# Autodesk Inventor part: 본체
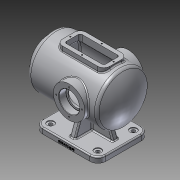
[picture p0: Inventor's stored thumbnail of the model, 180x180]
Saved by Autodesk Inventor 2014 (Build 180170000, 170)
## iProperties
Created: 2021-11
Part Number: 본체
Material: 알루미늄 6061
Document SubType Name: Modeling
Designer: kb542-04
Density: 2.71 g/cm^3
Appearance: 알루미늄 - 평지
Mass: 3553.65 g
Surface Area: 2404.16 cm^2
Volume: 1311.31 cm^3
Author: kb542-04
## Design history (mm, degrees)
sketch "스케치1"
  geometry: L1 (0, 0)-(210, 0); L2 (0, 32.5)-(25, 32.5); L3 (25, 32.5)-(25, 55); L4 (25, 55)-(181.239, 55); L5 (0, 32.5)-(0, 47.5); L6 (0, 47.5)-(10, 47.5); L7 (10, 47.5)-(10, 65); L8 (10, 65)-(181.239, 65); L9 (0, 101.95)-(170, 101.95); L10 (210, 0)-(210, 59.358); A1 r 100 centre (110, 0) between (210, 0) and (189.154, 61.111); A2 r 90 centre (110, 0) between (200, 0) and (181.239, 55); A3 r 10 centre (181.239, 55) between (189.154, 61.111) and (181.239, 65); 1 further point
  constraints: 20 end point, 7 point on circle, 5 parallel, 4 perpendicular, 3 centre point, 3 tangent, 2 point on line, 2 vertical alignment, 1 concentric, 1 horizontal
  dimensions: "d1" = 210 distance of L1.start L1.end; "d2" = 10 radial gap between concentric circles of A1 A2; "d3" = 25 distance of L2.start L2.end; "d4" = 65 diameter of L2 L1; "d5" = 95 diameter of L6 L1; "d6" = 130 diameter of L8 L1; "d7" = 10 distance between parallel lines of L7 L5; "d8" = 110 diameter of L4 L1; "d30" = 100 radius of A1; "d31" = 170 distance of L9.start L9.end; "d32" = 10 radius of A3
revolve "회전1" sketch "스케치1" stored, may be unused: angle "d10" = 90 deg
node "작업 평면1"
sketch "스케치2"
  geometry: L1 (50, -30)-(170, -30); L2 (170, -30)-(170, 30); L3 (170, 30)-(50, 30); L4 (50, 30)-(50, -30); L5 (60, -20)-(160, -20); L6 (160, -20)-(160, 20); L7 (160, 20)-(60, 20); L8 (60, 20)-(60, -20); 2 further points
  constraints: 16 end point, 4 parallel, 2 horizontal, 2 perpendicular, 1 horizontal alignment, 1 midpoint
  dimensions: "d12" = 120 distance of L2.end L3.end; "d13" = 10 distance between parallel lines of L7 L3; "d14" = 10 distance between parallel lines of L2 L6; "d15" = 10 distance between parallel lines of L4 L8; "d16" = 10 distance between parallel lines of L1 L5; "d17" = 50 distance from line of L4 point (0, 0); "d18" = 60 distance of L3.end L1.start
extrude "돌출1" join sketch "스케치2" stored distance "d19" = 10; taper "d20" = 0 deg
sketch "스케치3"
  geometry: L1 (170, 30)-(50, 30) reference; L2 (50, 30)-(50, -30) reference; L3 (50, -30)-(170, -30) reference; L4 (170, -30)-(170, 30) reference; L5 (55, 25)-(165, 25); L6 (165, 25)-(165, -25); L7 (165, -25)-(55, -25); L8 (55, -25)-(55, 25); 5 further points
  constraints: 8 end point, 4 midpoint, 3 other
  dimensions: "d21" = 50 distance of L7.end L5.start; "d22" = 55 horizontal distance of point (110, 25) point (55, 0) (derived)
hole "구멍1" sketch "스케치3" at (110, 25), (55, 0), (165, 0), (110, -25) diameter "d23" = 3.242; stored, may be unused: countersink angle "d27" = 90 deg, drill point angle "d29" = 118 deg; dims "d24" = 9, "d25" = 4, "d26" = 2, "d28" = 11
node "작업 평면2"
sketch "스케치4"
  geometry: L1 (30, 65)-(190, 65); L2 (190, 65)-(190, -65); L3 (190, -65)-(30, -65); L4 (30, -65)-(30, 65); L5 (0, -47.5)-(0, 47.5) reference; 2 further points
  constraints: 8 end point, 2 parallel, 1 horizontal, 1 horizontal alignment, 1 midpoint, 1 perpendicular
  dimensions: "d34" = 160 distance of L1.start L1.end; "d35" = 130 distance of L3.end L1.start; "d36" = 30 distance between parallel lines of L4 L5
extrude "돌출2" join sketch "스케치4" distance "d37" = 14; taper "d38" = 0 deg
fillet "모깎기1" dims "d39" = 20
sketch "스케치5"
  geometry: L1 (170, 7)-(170, -7); L2 (50, -7)-(50, 7); L3 (103, 50)-(117, 50); L4 (117, -50)-(103, -50); L5 (50, 7)-(103, 7); L6 (117, 7)-(170, 7); L7 (103, -50)-(103, -7); L8 (103, 7)-(103, 50); L9 (170, -7)-(117, -7); L10 (103, -7)-(50, -7); L11 (117, 50)-(117, 7); L12 (117, -7)-(117, -50); L13 (30, -45)-(30, 45) reference; 2 further points
  constraints: 24 end point, 10 parallel, 6 collinear, 4 perpendicular, 3 horizontal, 1 horizontal alignment, 1 midpoint
  dimensions: "d40" = 14 distance of L3.start L3.end; "d41" = 14 distance of L1.start L1.end; "d42" = 73 distance between parallel lines of L8 L13; "d43" = 120 distance between parallel lines of L1 L2; "d44" = 100 distance between parallel lines of L3 L4
extrude "돌출3" join sketch "스케치5" stored distance "d45" = 14; taper "d46" = 0 deg
feature "면 기울기1" dims angle "d47" = 20 deg
feature "면 기울기2" dims angle "d48" = 20 deg
feature "면 기울기3" dims angle "d49" = 20 deg
feature "면 기울기4" dims angle "d50" = 20 deg
node "작업 평면3"
sketch "스케치6"
  geometry: C1 r 40 at (-127, 0); 1 further point
  constraints: 1 centre point, 1 horizontal alignment
  dimensions: "d52" = 80 diameter of C1; "d53" = 127 distance of C1.centre point (0, 0)
extrude "돌출4" join sketch "스케치6" stored distance "d54" = 14; taper "d55" = 0 deg
hole "구멍2" diameter "d58" = 42; stored, may be unused: countersink angle "d62" = 90 deg, drill point angle "d64" = 118 deg; dims "d56" = 10, "d57" = 10, "d59" = 9, "d60" = 52, "d61" = 18, "d63" = 11
extrude "돌출5" cut sketch "스케치2" stored distance "d65" = 14; taper "d66" = 0 deg
sketch "스케치7"
  geometry: C1 r 40 at (0, 0) reference; A1 r 32.5 centre (0, 0) between (0, -32.5) and (-32.5, 0); 3 further points
  constraints: 4 point on circle, 2 horizontal alignment, 2 vertical alignment, 1 centre point, 1 coincident
  dimensions: "d67" = 65 diameter of A1
hole "구멍3" sketch "스케치7" at (0, -32.5), (-32.5, 0), (0, 32.5), (32.5, 0) diameter "d68" = 3.242; stored, may be unused: countersink angle "d72" = 90 deg, drill point angle "d74" = 118 deg; dims "d69" = 11, "d70" = 52, "d71" = 18, "d73" = 13
hole "구멍4" diameter "d77" = 9; stored, may be unused: countersink angle "d81" = 90 deg, drill point angle "d83" = 118 deg; dims "d75" = 10, "d76" = 10, "d78" = 11, "d79" = 18, "d80" = 2, "d82" = 13
hole "구멍5" diameter "d86" = 9; stored, may be unused: countersink angle "d90" = 90 deg, drill point angle "d92" = 118 deg; dims "d84" = 10, "d85" = 10, "d87" = 11, "d88" = 18, "d89" = 2, "d91" = 13
hole "구멍6" diameter "d95" = 9; stored, may be unused: countersink angle "d99" = 90 deg, drill point angle "d101" = 118 deg; dims "d93" = 10, "d94" = 10, "d96" = 11, "d97" = 18, "d98" = 2, "d100" = 13
hole "구멍7" diameter "d104" = 9; stored, may be unused: countersink angle "d108" = 90 deg, drill point angle "d110" = 118 deg; dims "d102" = 10, "d103" = 10, "d105" = 11, "d106" = 18, "d107" = 2, "d109" = 13
fillet "모깎기2" dims "d111" = 3, "d112" = 15, "d113" = 5
fillet "모깎기3" dims "d114" = 3
node "작업 평면5"
sketch "스케치8"
  geometry: L1 (0, 11)-(120, 11) reference; L2 (120, 0)-(0, 0) reference; 3 further points
  constraints: 1 midpoint, 1 vertical alignment, 1 other
  dimensions: "d116" = 5 distance from line of point (60, 5) L2
feature "엠보싱1" sketch "스케치8" dims "d12" = 120, "d13" = 10, "d14" = 10, "d15" = 10, "d16" = 10, "d17" = 50, "d18" = 60, "d117" = 0.5, "d118" = 0
chamfer "모따기1" distance "d119" = 1; stored, may be unused: second distance "d120" = 2, angle "d121" = 45 deg
fillet "모깎기4" dims "d122" = 10, "d123" = 3
sketch "스케치9"
  geometry: A1 r 40 centre (0, 0) between (40, 0) and (0, -40); 3 further points
  constraints: 4 point on circle, 2 horizontal alignment, 2 vertical alignment, 1 centre point, 1 coincident
  dimensions: "d124" = 80 diameter of A1
hole "구멍8" sketch "스케치9" at (40, 0), (0, -40), (0, 40), (-40, 0) diameter "d125" = 3.242; stored, may be unused: countersink angle "d129" = 90 deg, drill point angle "d131" = 118 deg; dims "d126" = 11, "d127" = 18, "d128" = 2, "d130" = 13
chamfer "모따기2" distance "d132" = 1; stored, may be unused: second distance "d133" = 2, angle "d134" = 45 deg
fillet "모깎기5" dims "d135" = 0.3
fillet "모깎기6" dims "d136" = 3
node "솔리드1"
mirror "대칭1"
node "작업 평면4"
other parameters: "d33" = -114, "d51" = 75, "d115" = 239.5
